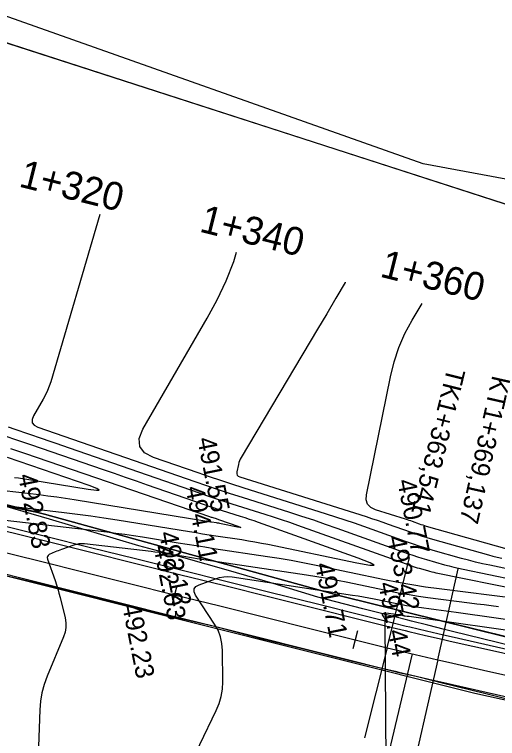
# Model space of a CAD drawing. Extents: x -636600 to -628587, y -1090963 to -1085869.
# Drawn here: x -629272 to -629220.1, y -1090435.6 to -1090357.8 of the extents above; entities that cross this region are included whole.
import ezdxf

# ---------------------------------------------------------------- set-up
doc = ezdxf.new("R2010")
doc.units = 0
for name, color, linetype in [('01_PARCELY_NÁVRH_PC', 7, 'Continuous'), ('21', 7, 'Continuous'), ('42', 7, 'Continuous'), ('dno příkopu', 7, 'Continuous'), ('Ex_Major Contours', 7, 'Continuous'), ('Ex_Minor Contours', 7, 'Continuous'), ('HEKTOMETRY20', 7, 'Continuous'), ('HL_BODY', 7, 'Continuous'), ('koty_vše', 7, 'Continuous'), ('PARCELY_NÁVRH_SILNICE_ŽELEZNICE', 7, 'Continuous'), ('POLOMERY', 7, 'Continuous'), ('situace_osa', 7, 'Continuous'), ('situace_těleso', 7, 'Continuous'), ('situace_vozovka', 7, 'Continuous'), ('VRCHOLY', 7, 'Continuous')]:
    doc.layers.add(name, color=color, linetype=linetype)

msp = doc.modelspace()

# ---------------------------------------------------------------- linework, layer by layer
at = {"layer": '01_PARCELY_NÁVRH_PC'}
msp.add_lwpolyline([(-629351.806, -1090398.382), (-629222.518, -1090430.761), (-629186.936, -1090438.561), (-629183.24, -1090440.676), (-629180.737, -1090444.12), (-629185.442, -1090428.103), (-629188.944, -1090431.171), (-629204.969, -1090428.241), (-629236.985, -1090420.294), (-629268.755, -1090411.534), (-629342.71, -1090393.203)], dxfattribs=at)
at = {"layer": '21'}
for p, q in [((-629214.576, -1090379.723), (-629277.106, -1090359.525)), ((-629342.71, -1090393.203), (-629268.755, -1090411.534)), ((-629268.755, -1090411.534), (-629236.985, -1090420.294)), ((-629236.985, -1090420.294), (-629213.841, -1090425.963))]:
    msp.add_line(p, q, dxfattribs=at)
at = {"layer": '42'}
for p, q in [((-629228.066, -1090373.895), (-629288.267, -1090352.593)), ((-629200.666, -1090378.974), (-629228.066, -1090373.895)), ((-629268.755, -1090411.534), (-629295.611, -1090406.061))]:
    msp.add_line(p, q, dxfattribs=at)
at = {"layer": 'dno příkopu'}
msp.add_lwpolyline([(-629273.524, -1090412.677), (-629268.672, -1090413.887), (-629263.821, -1090415.097), (-629258.969, -1090416.306), (-629254.118, -1090417.516), (-629249.266, -1090418.726), (-629244.415, -1090419.935), (-629239.563, -1090421.145), (-629234.712, -1090422.355), (-629231.277, -1090423.211), (-629229.875, -1090423.556), (-629229.485, -1090423.651), (-629227.69, -1090424.077), (-629225.892, -1090424.49), (-629225.05, -1090424.68), (-629220.172, -1090425.781), (-629215.295, -1090426.882)], dxfattribs=at)
at = {"layer": 'Ex_Major Contours'}
for points in [[(-629262.826, -1090379.327), (-629268.097, -1090397.29), (-629268.256, -1090397.777), (-629268.443, -1090398.253), (-629268.659, -1090398.716), (-629268.903, -1090399.167), (-629269.935, -1090400.948), (-629270.1, -1090401.358), (-629270.079, -1090401.7), (-629269.872, -1090401.972), (-629269.479, -1090402.175), (-629252.619, -1090408.029), (-629251.351, -1090408.465), (-629250.079, -1090408.89), (-629248.805, -1090409.307), (-629247.527, -1090409.714), (-629242.411, -1090411.324), (-629241.134, -1090411.733), (-629239.861, -1090412.154), (-629238.592, -1090412.588), (-629237.328, -1090413.033), (-629229.65, -1090415.781), (-629229.169, -1090415.948), (-629228.685, -1090416.108), (-629228.199, -1090416.259), (-629227.71, -1090416.402), (-629225.75, -1090416.957), (-629225.259, -1090417.091), (-629224.765, -1090417.216), (-629224.27, -1090417.332), (-629223.772, -1090417.439), (-629218.233, -1090418.576)], [(-629219.955, -1090421.503), (-629220.735, -1090421.394), (-629221.515, -1090421.288), (-629222.295, -1090421.185), (-629223.076, -1090421.084), (-629227.555, -1090420.512), (-629228.56, -1090420.374), (-629229.562, -1090420.216), (-629230.561, -1090420.039), (-629231.556, -1090419.842), (-629236.167, -1090418.884), (-629237.268, -1090418.663), (-629238.371, -1090418.457), (-629239.478, -1090418.267), (-629240.587, -1090418.092), (-629252.347, -1090416.32), (-629252.761, -1090416.257), (-629253.175, -1090416.192), (-629253.588, -1090416.127), (-629254.001, -1090416.06), (-629255.654, -1090415.791), (-629256.067, -1090415.726), (-629256.481, -1090415.666), (-629256.896, -1090415.61), (-629257.311, -1090415.559), (-629264.481, -1090414.724), (-629264.772, -1090414.707), (-629265.058, -1090414.723), (-629265.341, -1090414.772), (-629265.62, -1090414.854), (-629266.952, -1090415.33), (-629267.117, -1090415.391), (-629267.28, -1090415.454), (-629267.443, -1090415.521), (-629267.603, -1090415.591), (-629268.245, -1090415.877), (-629268.378, -1090415.961), (-629268.456, -1090416.067), (-629268.48, -1090416.198), (-629268.448, -1090416.352), (-629267.626, -1090418.675), (-629267.475, -1090419.119), (-629267.335, -1090419.566), (-629267.206, -1090420.017), (-629267.089, -1090420.471), (-629266.548, -1090422.674), (-629266.462, -1090423.19), (-629266.459, -1090423.699), (-629266.54, -1090424.202), (-629266.705, -1090424.698), (-629268.479, -1090428.94), (-629268.802, -1090429.821), (-629269.042, -1090430.719), (-629269.201, -1090431.636), (-629269.277, -1090432.571), (-629269.422, -1090436.513)]]:
    msp.add_lwpolyline(points, dxfattribs=at)
at = {"layer": 'Ex_Minor Contours'}
for points in [[(-629217.717, -1090417.674), (-629220.898, -1090417.021), (-629221.666, -1090416.856), (-629222.43, -1090416.677), (-629223.191, -1090416.484), (-629223.949, -1090416.277), (-629226.972, -1090415.421), (-629227.726, -1090415.2), (-629228.476, -1090414.967), (-629229.222, -1090414.722), (-629229.963, -1090414.463), (-629234.44, -1090412.861), (-629235.435, -1090412.511), (-629236.432, -1090412.17), (-629237.433, -1090411.839), (-629238.437, -1090411.517), (-629247.401, -1090408.696), (-629248.614, -1090408.309), (-629249.825, -1090407.914), (-629251.032, -1090407.509), (-629252.236, -1090407.096), (-629257.048, -1090405.425), (-629258.021, -1090404.922), (-629258.534, -1090404.248), (-629258.586, -1090403.403), (-629258.177, -1090402.386), (-629251.263, -1090390.456), (-629250.194, -1090388.479), (-629249.25, -1090386.448), (-629248.429, -1090384.365), (-629248.11, -1090383.385)], [(-629236.442, -1090386.603), (-629236.456, -1090386.626), (-629237.44, -1090388.307), (-629238.429, -1090389.984), (-629239.424, -1090391.658), (-629247.632, -1090405.426), (-629247.729, -1090405.607), (-629247.81, -1090405.793), (-629247.875, -1090405.986), (-629247.924, -1090406.184), (-629248.088, -1090406.993), (-629248.099, -1090407.177), (-629248.051, -1090407.327), (-629247.943, -1090407.441), (-629247.776, -1090407.52), (-629234.194, -1090411.795), (-629233.598, -1090411.986), (-629233.003, -1090412.183), (-629232.409, -1090412.385), (-629231.818, -1090412.594), (-629229.458, -1090413.439), (-629228.866, -1090413.645), (-629228.271, -1090413.841), (-629227.673, -1090414.027), (-629227.071, -1090414.203), (-629221.055, -1090415.907), (-629220.579, -1090416.037), (-629220.1, -1090416.158), (-629219.62, -1090416.271)], [(-629218.128, -1090415.546), (-629227.687, -1090412.838), (-629227.879, -1090412.782), (-629228.069, -1090412.723), (-629228.258, -1090412.661), (-629228.446, -1090412.595), (-629229.196, -1090412.327), (-629229.384, -1090412.26), (-629229.573, -1090412.196), (-629229.762, -1090412.133), (-629229.952, -1090412.073), (-629233.188, -1090411.054), (-629233.7, -1090410.811), (-629234.03, -1090410.46), (-629234.178, -1090410.001), (-629234.144, -1090409.436), (-629231.583, -1090396.764), (-629231.19, -1090395.166), (-629230.667, -1090393.618), (-629230.015, -1090392.121), (-629229.232, -1090390.674), (-629228.166, -1090388.885)], [(-629217.466, -1090419.741), (-629226.646, -1090417.858), (-629226.874, -1090417.809), (-629227.1, -1090417.756), (-629227.326, -1090417.698), (-629227.551, -1090417.637), (-629228.448, -1090417.383), (-629228.672, -1090417.317), (-629228.895, -1090417.248), (-629229.116, -1090417.175), (-629229.336, -1090417.099), (-629241.537, -1090412.732), (-629242.41, -1090412.425), (-629243.286, -1090412.126), (-629244.164, -1090411.835), (-629245.045, -1090411.553), (-629248.575, -1090410.442), (-629249.457, -1090410.161), (-629250.336, -1090409.874), (-629251.214, -1090409.58), (-629252.089, -1090409.279), (-629266.07, -1090404.425), (-629266.798, -1090404.172), (-629267.527, -1090403.921), (-629268.256, -1090403.67), (-629268.986, -1090403.42), (-629271.904, -1090402.422), (-629272.634, -1090402.174)], [(-629273.915, -1090410.494), (-629266.654, -1090411.34), (-629265.226, -1090411.515), (-629263.799, -1090411.705), (-629262.376, -1090411.913), (-629260.954, -1090412.136), (-629253.174, -1090413.404), (-629252.472, -1090413.517), (-629251.769, -1090413.629), (-629251.066, -1090413.738), (-629250.363, -1090413.845), (-629247.549, -1090414.269), (-629246.846, -1090414.38), (-629246.145, -1090414.5), (-629245.446, -1090414.631), (-629244.749, -1090414.771), (-629235.188, -1090416.758), (-629233.81, -1090417.011), (-629233.327, -1090417.013), (-629233.74, -1090416.763), (-629235.048, -1090416.26), (-629245.747, -1090412.431), (-629246.228, -1090412.262), (-629246.71, -1090412.097), (-629247.194, -1090411.937), (-629247.679, -1090411.782), (-629249.624, -1090411.17), (-629250.109, -1090411.015), (-629250.593, -1090410.857), (-629251.077, -1090410.695), (-629251.559, -1090410.53), (-629257.695, -1090408.399), (-629258.878, -1090407.989), (-629260.062, -1090407.58), (-629261.246, -1090407.173), (-629262.431, -1090406.767), (-629270.244, -1090404.095), (-629271.941, -1090403.517), (-629273.641, -1090402.943)], [(-629272.41, -1090404.462), (-629270.905, -1090404.974), (-629253.033, -1090411.086), (-629252.814, -1090411.161), (-629252.596, -1090411.236), (-629252.378, -1090411.311), (-629252.159, -1090411.387), (-629251.028, -1090411.78), (-629250.939, -1090411.81), (-629250.85, -1090411.84), (-629250.761, -1090411.869), (-629250.672, -1090411.898), (-629250.313, -1090412.011), (-629250.224, -1090412.039), (-629250.135, -1090412.069), (-629250.046, -1090412.099), (-629249.957, -1090412.13), (-629247.985, -1090412.836), (-629247.744, -1090412.929), (-629247.667, -1090412.975), (-629247.756, -1090412.975), (-629248.01, -1090412.928), (-629249.773, -1090412.562), (-629249.902, -1090412.536), (-629250.03, -1090412.512), (-629250.16, -1090412.49), (-629250.289, -1090412.469), (-629250.808, -1090412.391), (-629250.938, -1090412.371), (-629251.067, -1090412.351), (-629251.197, -1090412.331), (-629251.326, -1090412.31), (-629265.588, -1090409.985), (-629266.521, -1090409.839), (-629267.455, -1090409.703), (-629268.391, -1090409.577), (-629269.329, -1090409.463), (-629273.082, -1090409.026)], [(-629272.004, -1090407.585), (-629271.557, -1090407.64), (-629271.111, -1090407.7), (-629270.666, -1090407.764), (-629270.221, -1090407.834), (-629264.07, -1090408.837), (-629263.184, -1090408.956), (-629262.872, -1090408.932), (-629263.135, -1090408.763), (-629263.973, -1090408.45), (-629272.755, -1090405.447)], [(-629275.201, -1090411.91), (-629262.066, -1090413.44), (-629261.102, -1090413.558), (-629260.14, -1090413.687), (-629259.18, -1090413.826), (-629258.221, -1090413.977), (-629254.389, -1090414.602), (-629253.43, -1090414.756), (-629252.472, -1090414.908), (-629251.512, -1090415.057), (-629250.553, -1090415.203), (-629244.809, -1090416.069), (-629243.533, -1090416.27), (-629242.26, -1090416.489), (-629240.991, -1090416.726), (-629239.724, -1090416.98), (-629232.225, -1090418.538), (-629230.76, -1090418.828), (-629229.289, -1090419.089), (-629227.814, -1090419.321), (-629226.334, -1090419.525), (-629217.86, -1090420.606)], [(-629253.817, -1090439.933), (-629250.302, -1090432.64), (-629249.993, -1090431.895), (-629249.774, -1090431.13), (-629249.644, -1090430.344), (-629249.605, -1090429.539), (-629249.626, -1090426.196), (-629249.684, -1090425.435), (-629249.846, -1090424.707), (-629250.113, -1090424.009), (-629250.486, -1090423.344), (-629252.519, -1090420.231), (-629252.689, -1090419.866), (-629252.685, -1090419.559), (-629252.506, -1090419.309), (-629252.152, -1090419.117), (-629250.389, -1090418.462), (-629249.945, -1090418.327), (-629249.495, -1090418.251), (-629249.04, -1090418.234), (-629248.578, -1090418.275), (-629235.649, -1090420.223), (-629235.064, -1090420.315), (-629234.481, -1090420.416), (-629233.899, -1090420.524), (-629233.318, -1090420.641), (-629230.886, -1090421.146), (-629230.361, -1090421.25), (-629229.835, -1090421.343), (-629229.306, -1090421.427), (-629228.776, -1090421.499), (-629226.652, -1090421.77), (-629226.121, -1090421.839), (-629225.591, -1090421.909), (-629225.06, -1090421.982), (-629224.53, -1090422.056), (-629215.919, -1090423.273)], [(-629215.915, -1090424.473), (-629229.556, -1090422.545), (-629229.611, -1090422.537), (-629229.666, -1090422.529), (-629229.721, -1090422.522), (-629229.777, -1090422.515), (-629229.997, -1090422.487), (-629230.052, -1090422.479), (-629230.107, -1090422.471), (-629230.162, -1090422.461), (-629230.217, -1090422.45), (-629230.469, -1090422.397), (-629230.53, -1090422.385), (-629230.59, -1090422.374), (-629230.651, -1090422.364), (-629230.712, -1090422.354), (-629232.056, -1090422.152), (-629232.104, -1090422.147), (-629232.151, -1090422.149), (-629232.198, -1090422.157), (-629232.244, -1090422.171), (-629232.427, -1090422.239), (-629232.464, -1090422.259), (-629232.482, -1090422.285), (-629232.483, -1090422.317), (-629232.465, -1090422.355), (-629232.254, -1090422.678), (-629232.215, -1090422.748), (-629232.187, -1090422.82), (-629232.171, -1090422.896), (-629232.165, -1090422.975), (-629232.033, -1090443.306)]]:
    msp.add_lwpolyline(points, dxfattribs=at)
at = {"layer": 'HEKTOMETRY20'}
for points in [[(-629254.541, -1090419.214), (-629255.025, -1090421.155)], [(-629235.135, -1090424.053), (-629235.619, -1090425.993)]]:
    msp.add_lwpolyline(points, dxfattribs=at)
at = {"layer": 'HL_BODY'}
for points in [[(-629231.942, -1090425.88), (-629229.523, -1090416.177)], [(-629226.497, -1090427.173), (-629224.296, -1090417.418)]]:
    msp.add_lwpolyline(points, dxfattribs=at)
at = {"layer": 'PARCELY_NÁVRH_SILNICE_ŽELEZNICE'}
for points in [[(-629605.575, -1090296.86), (-629591.052, -1090304.21), (-629561.855, -1090321.748), (-629545.359, -1090334.769), (-629498.696, -1090345.634), (-629454.812, -1090359.914), (-629438.615, -1090363.656), (-629342.71, -1090393.203), (-629268.755, -1090411.534), (-629236.985, -1090420.294), (-629204.969, -1090428.241), (-629188.944, -1090431.171), (-629176.974, -1090420.684), (-629160.151, -1090425.271), (-629130.105, -1090434.667)], [(-629130.105, -1090419.706), (-629163.633, -1090410.944), (-629180.345, -1090404.602), (-629192.435, -1090400.444), (-629193.855, -1090391.683), (-629214.576, -1090379.723), (-629277.106, -1090359.525), (-629343.27, -1090339.049), (-629375.976, -1090328.394), (-629483.018, -1090296.86)]]:
    msp.add_lwpolyline(points, dxfattribs=at)
at = {"layer": 'POLOMERY'}
for points in [[(-629231.942, -1090425.88), (-629234.361, -1090435.583)], [(-629226.497, -1090427.173), (-629228.699, -1090436.927)]]:
    msp.add_lwpolyline(points, dxfattribs=at)
at = {"layer": 'situace_osa'}
msp.add_lwpolyline([(-629274.189, -1090415.346), (-629269.338, -1090416.555), (-629264.486, -1090417.765), (-629259.635, -1090418.975), (-629254.783, -1090420.184), (-629249.932, -1090421.394), (-629245.08, -1090422.604), (-629240.229, -1090423.813), (-629235.377, -1090425.023), (-629231.942, -1090425.88), (-629230.525, -1090426.229), (-629230.13, -1090426.324), (-629228.315, -1090426.755), (-629226.497, -1090427.173), (-629225.655, -1090427.363), (-629220.778, -1090428.464), (-629215.901, -1090429.564)], dxfattribs=at)
at = {"layer": 'situace_těleso'}
for points in [[(-629215.217, -1090426.537), (-629220.069, -1090425.324), (-629224.924, -1090424.122), (-629225.762, -1090423.915), (-629227.548, -1090423.471), (-629229.331, -1090423.015), (-629229.719, -1090422.914), (-629231.115, -1090422.564), (-629234.548, -1090421.696), (-629239.39, -1090420.449), (-629244.181, -1090418.996), (-629248.982, -1090417.584), (-629253.797, -1090416.229), (-629258.627, -1090414.933), (-629263.418, -1090413.482), (-629268.217, -1090412.062), (-629273.024, -1090410.672)], [(-629274.77, -1090417.675), (-629269.908, -1090418.843), (-629265.051, -1090420.029), (-629260.198, -1090421.233), (-629255.345, -1090422.438), (-629250.477, -1090423.583), (-629245.638, -1090424.842), (-629240.787, -1090426.051), (-629235.932, -1090427.249), (-629232.493, -1090428.09), (-629231.061, -1090428.434), (-629230.662, -1090428.528), (-629228.829, -1090428.954), (-629227.003, -1090429.411), (-629226.164, -1090429.617), (-629221.31, -1090430.819), (-629216.452, -1090432.008)]]:
    msp.add_lwpolyline(points, dxfattribs=at)
at = {"layer": 'situace_vozovka'}
for points in [[(-629273.645, -1090413.163), (-629268.793, -1090414.372), (-629263.942, -1090415.582), (-629259.09, -1090416.792), (-629254.239, -1090418.001), (-629249.387, -1090419.211), (-629244.536, -1090420.421), (-629239.684, -1090421.63), (-629234.833, -1090422.84), (-629231.398, -1090423.697), (-629229.993, -1090424.042), (-629229.602, -1090424.137), (-629227.804, -1090424.564), (-629226.002, -1090424.978), (-629225.16, -1090425.168), (-629220.283, -1090426.269), (-629215.405, -1090427.37)], [(-629274.733, -1090417.529), (-629269.882, -1090418.739), (-629265.03, -1090419.948), (-629260.179, -1090421.158), (-629255.328, -1090422.368), (-629250.476, -1090423.577), (-629245.625, -1090424.787), (-629240.773, -1090425.997), (-629235.922, -1090427.206), (-629232.486, -1090428.063), (-629231.056, -1090428.415), (-629230.658, -1090428.511), (-629228.827, -1090428.946), (-629226.993, -1090429.367), (-629226.151, -1090429.558), (-629221.273, -1090430.658), (-629216.396, -1090431.759)]]:
    msp.add_lwpolyline(points, dxfattribs=at)
at = {"layer": 'VRCHOLY'}
msp.add_lwpolyline([(-629229.227, -1090426.557), (-629233.848, -1090446.015)], dxfattribs=at)

# ---------------------------------------------------------------- texts
at = {"layer": 'HEKTOMETRY20'}
for s, p in [('1+320', (-629271.624, -1090376.306)), ('1+340', (-629252.218, -1090381.145)), ('1+360', (-629232.813, -1090385.984))]:
    msp.add_text(s, height=3, rotation=345.99927, dxfattribs=at).set_placement(p)
at = {"layer": 'HL_BODY'}
for s, rotation, p in [('TK1+363,541', 255.99927, (-629225.449, -1090395.705)), ('KT1+369,137', 257.28176, (-629220.608, -1090396.538))]:
    msp.add_text(s, height=2, rotation=rotation, dxfattribs=at).set_placement(p)
at = {"layer": 'koty_vše'}
for s, p in [('491.55', (-629252.356, -1090403.435)), ('492.83', (-629271.621, -1090407.359)), ('490.77', (-629230.861, -1090407.938)), ('494.11', (-629253.621, -1090408.677)), ('492.12', (-629256.469, -1090413.547)), ('493.42', (-629231.937, -1090414.03)), ('492.03', (-629257.062, -1090415.028)), ('491.71', (-629239.696, -1090416.907)), ('491.44', (-629232.893, -1090418.977)), ('492.23', (-629260.437, -1090421.3))]:
    msp.add_text(s, height=2, rotation=281.21136, dxfattribs=at).set_placement(p)

doc.saveas('drawing.dxf')
